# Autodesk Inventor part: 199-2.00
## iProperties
Created: 2007-06
Part Number: 199-2.00
Document SubType Name: Modeling
Designer: btaylor
Density: 1 g/cm^3
Author: btaylor
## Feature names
1. Extrusion1
2. Extrusion2
3. Extrusion3
4. Sweep1
5. Extrusion4
6. Fillet1
7. Fillet2
8. Fillet3
9. Fillet4
10. Extrusion5
11. Extrusion6
12. Extrusion7
13. Extrusion8
14. Sweep2
15. Fillet5
16. Fillet6
17. Fillet7
18. Fillet8
19. Chamfer1
20. Chamfer2
21. Chamfer3
22. Fillet9
23. Fillet10
24. Fillet11
